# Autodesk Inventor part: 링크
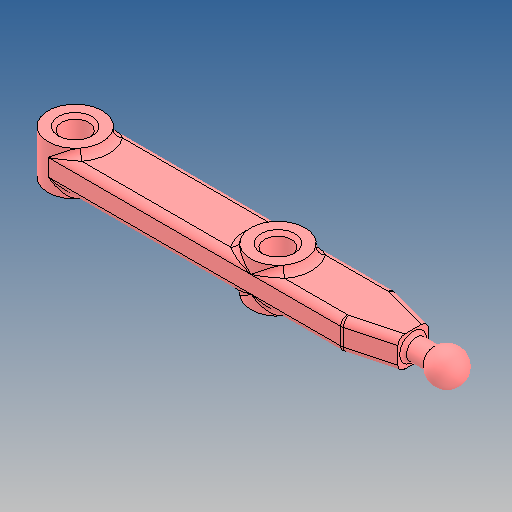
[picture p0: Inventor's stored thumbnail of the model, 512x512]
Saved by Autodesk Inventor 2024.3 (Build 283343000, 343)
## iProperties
Created: 2025-06
Part Number: 링크
Material: 강철, 탄소
Document SubType Name: Modeling
Designer: user
Density: 7.85 g/cm^3
Appearance: 기본값
Author: jhkim
Sending System: Autodesk Inventor 2026
Preprocessor: ST-DEVELOPER v20.1
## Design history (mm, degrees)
node "링크1"
node "솔리드2"
node "솔리드1"
